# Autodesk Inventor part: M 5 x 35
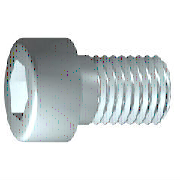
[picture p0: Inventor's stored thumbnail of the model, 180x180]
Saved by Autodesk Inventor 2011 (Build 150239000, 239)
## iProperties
IsCustomPart: 0
Company: 한국ATC센터
Created: 2014-12
Part Number: M 5 x 35
Material: 강, 연강
Description: 6각머리 태핑 나사
Document SubType Name: Modeling
Standard: KS B 1003
Designer: KYOUNG IL JANG
Standards Organization: KS
Language: ko-KR
Size Designation: M 5 x 35
Categories: <MemberInstance><Categories><Category DisplayName="조임쇠" InternalName="e4da775c-781d-43d5-af7c-5136215cf5a6" Mnemonic="FSTN"><Category DisplayName="볼트" InternalN
Density: 7.86 g/cm^3
Mass: 7.27786 g
Surface Area: 8.23857 cm^2
Volume: 0.925936 cm^3
Author: KYOUNG IL JANG
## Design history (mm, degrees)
workplane "Work Plane1"
fillet "Fillet2" dims "d30" = 0.1 (= R)
revolve "본체" stored, may be unused: angle "d10" = 90 deg
sketch "스케치2"
  geometry: L1 (0, -5.95)-(0, 5.95) reference; L2 (-5.95, 0)-(5.95, 0) reference; L3 (2.309, 0)-(1.155, -2); L4 (1.155, -2)-(-1.155, -2); L5 (-1.155, -2)-(-2.309, 0); L6 (-2.309, 0)-(-1.155, 2); L7 (-1.155, 2)-(1.155, 2); L8 (1.155, 2)-(2.309, 0); 2 further points
  constraints: 12 end point, 1 coincident, 1 horizontal alignment, 1 point on line, 12 other
extrude "슬롯" join sketch "스케치2" stored distance "d11" = 10; taper "d12" = 0 deg
body "Solid1"
fillet "모깎기1" dims "d17" = 0.5 (= RR)
feature "스레드" dims "d13" = 22 (= GEL), "d14" = 0
chamfer "모따기1" distance "d15" = 0.49076 (= -0.5 x SPD + 0.5 x GD); stored, may be unused: second distance "d16" = 0.49076 (= GUL), angle "d27" = 45 deg
sketch "스케치1"
  geometry: L1 (-1.167, 0)-(35, 0); L2 (35, 0)-(35, 2.5); L3 (35, 2.5)-(13, 2.5); L4 (13, 2.5)-(12.509, 2.5); L5 (12.509, 2.5)-(0, 2.5); L6 (0, 2.5)-(0, 4.25); L7 (0, 4.25)-(-5, 4.25); L8 (-5, 4.25)-(-5, 2.309); L9 (-5, 2.309)-(-2.5, 2.309); L10 (-2.5, 2.309)-(-1.167, 0); L11 (-13, 0)-(43, 0) reference; L12 (0, -0.85)-(0, 5.1) reference; L13 (13, 2.5)-(0, 2.5)
  constraints: 22 end point, 6 parallel, 2 collinear, 2 perpendicular, 1 horizontal, 1 point on line
  dimensions: "d1" = 22 distance from line of L3.end L2 (= GEL); "d2" = 0.49086 distance of L4.end L3.end (computed from GAL); "d3" = 5 distance between parallel lines of L8 L6 (= KOH); "d4" = 2.5 distance of L8.end L9.end (= INTI); "d5" = 60 deg angle of L10 L1; "d6" = 5 diameter of L3 L1 (= GD); "d7" = 5 diameter of L5 L1 (= BDM); "d8" = 4.6188 diameter of L9 L1 (= 1.1547 x SW); "d9" = 8.5 diameter of L7 L1 (= KOD); "d26" = 35 distance between parallel lines of L12 L2 (= NLG)
other parameters: "GD" = 5 (= NND) [user parameter; used in 2 equation terms], "NLG" = 35 [user parameter; used in 1 equation term], "GEL" = 22 [user parameter; used in 2 equation terms], "KOD" = 8.5 [user parameter; used in 1 equation term], "KOH" = 5 [user parameter; used in 1 equation term], "INTI" = 2.5 [user parameter; used in 1 equation term], "GAL" = 0.49076 (= 0.61345 x PTC) [user parameter; used in 1 equation term], "GUL" = 0.49076 (= 0.61345 x PTC) [user parameter; used in 1 equation term], "BDM" = 5 (= NND) [user parameter; used in 1 equation term], "SW" = 4 [user parameter; used in 2 equation terms], "RR" = 0.5 [user parameter; used in 1 equation term], "SPD" = 4.01848 (= NND - 1.2269 x PTC) [user parameter; used in 1 equation term], "d19" = 0, "d28" = 0, "d29" = 0, "R" = 0.1 [user parameter; used in 1 equation term], "PHH" = 0.2 [user parameter], "GD1" = 4.01848 (= THREADDIA - 1.2269 x PTC) [user parameter], "THREADDIA" = 5 [user parameter; used in 1 equation term], "FAWI" = 45 deg [user parameter], "TPU" = 12.5 (computed from PTC) [user parameter], "PTC" = 0.8 [user parameter; used in 5 equation terms], "NND" = 5 [user parameter; used in 3 equation terms], "TOA" = 30 deg [user parameter], "E0" = 4.62 (= 1.155 x SW) [user parameter]
